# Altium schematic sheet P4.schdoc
size 297 x 209 mm; Symbol: Drawing-Symbol_A4; Company: 嘉立创EDA; Version: V1.0; Page Size: A4; @Project Name: 远程开机卡; @Update Date: 2026-06-19; @Create Date: 2026-06-19; Device: Drawing-Symbol_A4; @Board Name: cm4_1; @Page Name: P3; @Create Time: 20:06:20; @Page Count: 7; @Page No: 0; @Schematic Name: SCH_1; @Update Time: 20:06:20; @Assembly Variant: Basic; Border: 1; Title Block Position: 3; Size: A4; Width: 1170; Height: 825; Region Start: 1; X Region Count: 6; Y Region Count: 4; Blade Width: 10
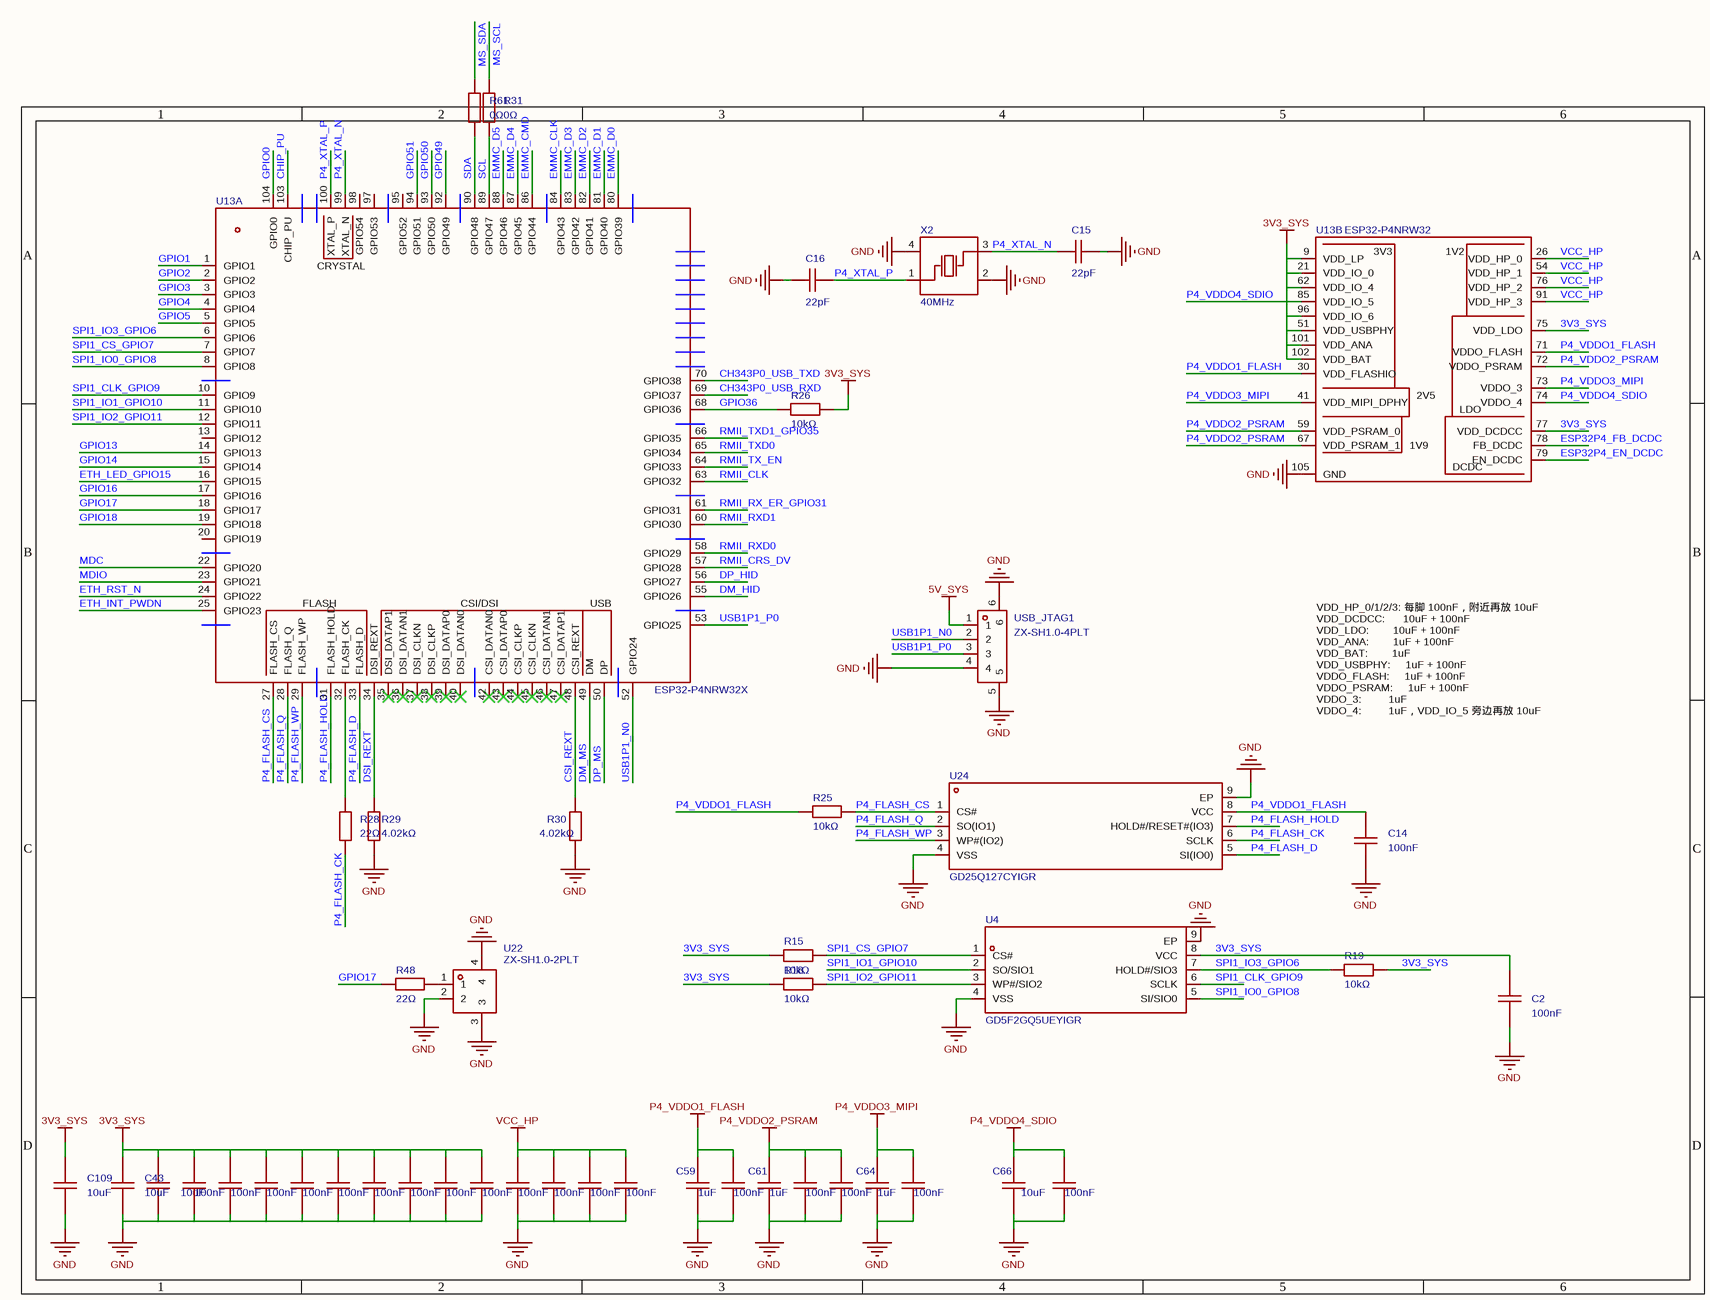
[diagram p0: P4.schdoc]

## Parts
C2  100nF  [C0402 去耦电容]
C14  100nF  [C0402 去耦电容]
C15  22pF  [C0402]
C16  22pF  [C0402]
C43  10uF  [C0805]
C44  10uF  [C0805]
C45  100nF  [C0402 去耦电容]
C46  100nF  [C0402 去耦电容]
C47  100nF  [C0402 去耦电容]
C48  100nF  [C0402 去耦电容]
C49  100nF  [C0402 去耦电容]
C50  100nF  [C0402 去耦电容]
C51  100nF  [C0402 去耦电容]
C52  100nF  [C0402 去耦电容]
C53  100nF  [C0402 去耦电容]
C55  100nF  [C0402 去耦电容]
C56  100nF  [C0402 去耦电容]
C57  100nF  [C0402 去耦电容]
C58  100nF  [C0402 去耦电容]
C59  1uF  [C0402]
C60  100nF  [C0402 去耦电容]
C61  1uF  [C0402]
C62  100nF  [C0402 去耦电容]
C63  100nF  [C0402 去耦电容]
C64  1uF  [C0402]
C65  100nF  [C0402 去耦电容]
C66  10uF  [C0805]
C67  100nF  [C0402 去耦电容]
C109  10uF  [C0805]
R15  10kΩ  [R0402]
R18  10kΩ  [R0402]
R19  10kΩ  [R0402]
R25  10kΩ  [R0402]
R26  10kΩ  [R0402]
R28  22Ω  [R0402]
R29  4.02kΩ  [R0402]
R30  4.02kΩ  [R0402]
R31  0Ω  [R0402]
R48  22Ω  [R0402]
R61  0Ω  [R0402]
U4  GD5F2GQ5UEYIGR  [WSON-8_L6.0-W8.0-P1.27-BL-EP]
U13  ESP32-P4NRW32X  [QFN-104_L10.0-W10.0-P0.35-TL-EP7.5]  (parts A,B of 2)
U22  ZX-SH1.0-2PLT  [CONN-SMD_2P-P1.00_MEGASTAR_ZX-SH1.0-2PLT]
U24  GD25Q127CYIGR  [WSON-8_L6.0-W8.0-P1.27-BL-EP]
USB_JTAG1  ZX-SH1.0-4PLT  [CONN-SMD_4P-P1.00_ZX-SH1.0-4PLN]
X2  40MHz  [OSC-SMD_4P-L3.2-W2.5-BL_SIT8008BI]

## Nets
3V3_SYS: C2.1 C43.2 C44.2 C45.2 C46.2 C47.2 C48.2 C49.2 C50.2 C51.2 C52.2 C53.2 C109.2 R15.1 R18.1 R19.2 R26.2 U4.8(VCC) U13.9(VDD_LP) U13.21(VDD_IO_0) U13.51(VDD_USBPHY) U13.62(VDD_IO_4) U13.75(VDD_LDO) U13.77(VDD_DCDCC) U13.96(VDD_IO_6) U13.101(VDD_ANA) U13.102(VDD_BAT)
5V_SYS: USB_JTAG1.1
GND: C2.2 C14.2 C15.2 C16.1 C43.1 C44.1 C45.1 C46.1 C47.1 C48.1 C49.1 C50.1 C51.1 C52.1 C53.1 C55.1 C56.1 C57.1 C58.1 C59.1 C60.1 C61.1 C62.1 C63.1 C64.1 C65.1 C66.1 C67.1 C109.1 R29.1 R30.1 U4.4(VSS) U4.9(EP) U13.105(GND) U22.2 U22.3 U22.4 U24.4(VSS) U24.9(EP) USB_JTAG1.4 USB_JTAG1.5 USB_JTAG1.6 X2.2(GND) X2.4(GND)
P4_VDDO1_FLASH: C14.1 C59.2 C60.2 R25.1 U13.30(VDD_FLASHIO) U13.71(VDDO_FLASH) U24.8(VCC)
P4_VDDO2_PSRAM: C61.2 C62.2 C63.2 U13.59(VDD_PSRAM_0) U13.67(VDD_PSRAM_1) U13.72(VDDO_PSRAM)
P4_VDDO3_MIPI: C64.2 C65.2 U13.41(VDD_MIPI_DPHY) U13.73(VDDO_3)
P4_VDDO4_SDIO: C66.2 C67.2 U13.74(VDDO_4) U13.85(VDD_IO_5)
VCC_HP: C55.2 C56.2 C57.2 C58.2 U13.26(VDD_HP_0) U13.54(VDD_HP_1) U13.76(VDD_HP_2) U13.91(VDD_HP_3)
CH343P0_USB_RXD: U13.69(GPIO37)
CH343P0_USB_TXD: U13.70(GPIO38)
CHIP_PU: U13.103(CHIP_PU)
CSI_REXT: R30.2 U13.48(CSI_REXT)
DM_HID: U13.55(GPIO26)
DM_MS: U13.49(DM)
DP_HID: U13.56(GPIO27)
DP_MS: U13.50(DP)
DSI_REXT: R29.2 U13.34(DSI_REXT)
EMMC_CLK: U13.84(GPIO43)
EMMC_CMD: U13.86(GPIO44)
EMMC_D0: U13.80(GPIO39)
EMMC_D1: U13.81(GPIO40)
EMMC_D2: U13.82(GPIO41)
EMMC_D3: U13.83(GPIO42)
EMMC_D4: U13.87(GPIO45)
EMMC_D5: U13.88(GPIO46)
ESP32P4_EN_DCDC: U13.79(EN_DCDC)
ESP32P4_FB_DCDC: U13.78(FB_DCDC)
ETH_INT_PWDN: U13.25(GPIO23)
ETH_LED_GPIO15: U13.16(GPIO15)
ETH_RST_N: U13.24(GPIO22)
GPIO0: U13.104(GPIO0)
GPIO1: U13.1(GPIO1)
GPIO2: U13.2(GPIO2)
GPIO3: U13.3(GPIO3)
GPIO4: U13.4(GPIO4)
GPIO5: U13.5(GPIO5)
GPIO13: U13.14(GPIO13)
GPIO14: U13.15(GPIO14)
GPIO16: U13.17(GPIO16)
GPIO17: R48.1 U13.18(GPIO17)
GPIO18: U13.19(GPIO18)
GPIO36: R26.1 U13.68(GPIO36)
GPIO49: U13.92(GPIO49)
GPIO50: U13.93(GPIO50)
GPIO51: U13.94(GPIO51)
MDC: U13.22(GPIO20)
MDIO: U13.23(GPIO21)
MS_SCL: R31.1
MS_SDA: R61.1
P4_FLASH_CK: R28.1 U24.6(SCLK)
P4_FLASH_CS: R25.2 U13.27(FLASH_CS) U24.1(CS#)
P4_FLASH_D: U13.33(FLASH_D) U24.5(SI(IO0))
P4_FLASH_HOLD: U13.31(FLASH_HOLD) U24.7(HOLD#/RESET#(IO3))
P4_FLASH_Q: U13.28(FLASH_Q) U24.2(SO(IO1))
P4_FLASH_WP: U13.29(FLASH_WP) U24.3(WP#(IO2))
P4_XTAL_N: C15.1 U13.99(XTAL_N) X2.3(OSC2)
P4_XTAL_P: C16.2 U13.100(XTAL_P) X2.1(OSC1)
RMII_CLK: U13.63(GPIO32)
RMII_CRS_DV: U13.57(GPIO28)
RMII_RX_ER_GPIO31: U13.61(GPIO31)
RMII_RXD0: U13.58(GPIO29)
RMII_RXD1: U13.60(GPIO30)
RMII_TX_EN: U13.64(GPIO33)
RMII_TXD0: U13.65(GPIO34)
RMII_TXD1_GPIO35: U13.66(GPIO35)
SCL: R31.2 U13.89(GPIO47)
SDA: R61.2 U13.90(GPIO48)
SPI1_CLK_GPIO9: U4.6(SCLK) U13.10(GPIO9)
SPI1_CS_GPIO7: R15.2 U4.1(CS#) U13.7(GPIO7)
SPI1_IO0_GPIO8: U4.5(SI/SIO0) U13.8(GPIO8)
SPI1_IO1_GPIO10: U4.2(SO/SIO1) U13.11(GPIO10)
SPI1_IO2_GPIO11: R18.2 U4.3(WP#/SIO2) U13.12(GPIO11)
SPI1_IO3_GPIO6: R19.1 U4.7(HOLD#/SIO3) U13.6(GPIO6)
USB1P1_N0: U13.52(GPIO24) USB_JTAG1.2
USB1P1_P0: U13.53(GPIO25) USB_JTAG1.3
NetR28_2: R28.2 U13.32(FLASH_CK)
NetR48_2: R48.2 U22.1

Not connected (* = marked no-connect by the designer): U13 13(GPIO12) 20(GPIO19) 35(DSI_DATAP1)* 36(DSI_DATAN1)* 37(DSI_CLKN)* 38(DSI_CLKP)* 39(DSI_DATAP0)* 40(DSI_DATAN0)* 42(CSI_DATAN0)* 43(CSI_DATAP0)* 44(CSI_CLKP)* 45(CSI_CLKN)* 46(CSI_DATAN1)* 47(CSI_DATAP1)* 95(GPIO52) 97(GPIO53) 98(GPIO54)

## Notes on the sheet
- VDD_HP_0/1/2/3: 每脚 100nF，附近再放 10uF
  VDD_DCDCC:      10uF + 100nF
  VDD_LDO:        10uF + 100nF
  VDD_ANA:        1uF + 100nF
  VDD_BAT:        1uF
  VDD_USBPHY:     1uF + 100nF
  VDDO_FLASH:     1uF + 100nF
  VDDO_PSRAM:     1uF + 100nF
  VDDO_3:         1uF
  VDDO_4:         1uF，VDD_IO_5 旁边再放 10uF

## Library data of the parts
C2 C14 = CL05B104KO5NNNC: 容值:100nF;精度:±10%;额定电压:16V;温度系数:X7R;; Manufacturer: SAMSUNG(三星); Check: false; Add into BOM: yes; 3D Model: 36a51122f27c49738f86b3bfa98863e0; 3D Model Transform: 39.37,19.685,0,0,0,0,0,0,0; Tolerance: ±10%; Voltage Rating: 16V; Temperature Coefficient: X7R; ModelName: C0402_L1.0-W0.5-H0.5
C15 C16 = 0402CG220J500NT: 容值:22pF;精度:±5%;额定电压:50V;温度系数:C0G;; Manufacturer: FH(风华); Add into BOM: yes; 3D Model: 36a51122f27c49738f86b3bfa98863e0; 3D Model Transform: 39.37,19.685,0,0,0,0,0,0,0; Tolerance: ±5%; Voltage Rating: 50V; Temperature Coefficient: C0G; ModelName: C0402_L1.0-W0.5-H0.5
C43 C44 C66 C109 = CL21A106KAYNNNE_C15850: 容值:10uF;精度:±10%;额定电压:25V;温度系数:X5R;; Manufacturer: SAMSUNG(三星); Add into BOM: yes; 3D Model: 1ba041120af144c991958decab20d241; 3D Model Transform: 78.74,51.181,0,0,0,0,0,0.0005,0; Tolerance: ±10%; Voltage Rating: 25V; Temperature Coefficient: X5R; ModelName: C0805_L2.0-W1.3-H1.3
C45-C53 C55-C58 C60 C62 C63 C65 C67 = CL05B104KO5NNNC: 容值:100nF;精度:±10%;额定电压:16V;温度系数:X7R;; Manufacturer: SAMSUNG(三星); Symbol: Capacitance; Check: false; Add into BOM: yes; 3D Model Transform: 39.37,19.685,0,0,0,0,0,0,0; Tolerance: ±10%; Voltage Rating: 16V; Temperature Coefficient: X7R; 3D Model: 36a51122f27c49738f86b3bfa98863e00819f05c4eef4c71ace90d822a990e87; ModelName: C0402_L1.0-W0.5-H0.5
C59 C61 C64 = CL05A105KA5NQNC: 容值:1uF;精度:±10%;额定电压:25V;温度系数:X5R;; Manufacturer: SAMSUNG(三星); Symbol: Capacitance; Add into BOM: yes; 3D Model: 36a51122f27c49738f86b3bfa98863e0; 3D Model Transform: 39.37,19.685,0,0,0,0,0,0,0; Tolerance: ±10%; Voltage Rating: 25V; Temperature Coefficient: X5R; ModelName: C0402_L1.0-W0.5-H0.5
R15 R18 R19 R25 R26 = 0402WGF1002TCE: 电阻类型:厚膜电阻;阻值:10kΩ;精度:±1%;功率:62.5mW;工作电压:50V;温度系数:±100ppm/℃;; Manufacturer: UNI-ROYAL(厚声); Add into BOM: yes; 3D Model: 98c88bc2b9094f218f3a3e30a7012738; 3D Model Transform: 39.37,19.685,0,0,0,0,0,0,0; Tolerance: ±1%; Power(Watts): 62.5mW; Voltage-Supply(Max): 50V; ModelName: R0402_L1.0-W0.5-H0.4
R28 R48 = 0402WGF220JTCE: 电阻类型:厚膜电阻;阻值:22Ω;精度:±1%;功率:62.5mW;最大工作电压:50V;温度系数:±100ppm/℃;; Manufacturer: UNI-ROYAL(厚声); Add into BOM: yes; 3D Model: 98c88bc2b9094f218f3a3e30a7012738; 3D Model Transform: 39.37,19.685,0,0,0,0,0,0,0; Tolerance: ±1%; Power(Watts): 62.5mW; Overload Voltage (Max): 50V; ModelName: R0402_L1.0-W0.5-H0.4
R29 R30 = RMC04024.02K1%N: 电阻类型:厚膜电阻;阻值:4.02kΩ;精度:±1%;功率:62.5mW;工作电压:50V;温度系数:±100ppm/℃;; Manufacturer: Tyohm(幸亚电阻); Symbol: 电阻; Add into BOM: yes; 3D Model Transform: 39.37,19.685,0,0,0,0,0,0,0; Tolerance: ±1%; Power(Watts): 62.5mW; Voltage-Supply(Max): 50V; 3D Model: 98c88bc2b9094f218f3a3e30a70127380819f05c4eef4c71ace90d822a990e87; ModelName: R0402_L1.0-W0.5-H0.4
R31 R61 = 0402WGF0000TCE: 电阻类型:厚膜电阻;阻值:0Ω;精度:±1%;功率:62.5mW;工作电压:50V;温度系数:±800ppm/℃;; Manufacturer: UNI-ROYAL(厚声); Add into BOM: yes; 3D Model: 98c88bc2b9094f218f3a3e30a7012738; 3D Model Transform: 39.37,19.685,0,0,0,0,0,0,0; Tolerance: ±1%; Power(Watts): 62.5mW; Voltage-Supply(Max): 50V; ModelName: R0402_L1.0-W0.5-H0.4
U4 = GD5F2GQ5UEYIGR: 存储容量:2Gbit;时钟频率(fc):104MHz;工作电压:2.7V~3.6V;; Manufacturer: GigaDevice(兆易创新); AddInBom: yes; ModelId: b173dc61e57d4be286a8c115df50567b0819f05c4eef4c71ace90d822a990e87; ModelName: WSON-8_L6.0-W8.0-H0.8-P1.27; ModelTransform: 315.7474,236.22,0,90,0,0,0.005,0.016,0; Memory Size: 2Gbit; Interface: SPI; Clock Frequency: 104MHz; Page Program time (TPP): 300us; Block Erase Time(tBE): 3ms; Data Retention - TDR (Year): 10年; Standby Supply Current: 50uA; Program / Erase Cycles: 10万次
U13 = ESP32-P4NRW32_C22387510: 是一款高性能 MCU，支持超大片上内存，具有强大的图像和语音处理能力。该款 MCU 包含一个高性能（HP）系统和一个低功耗（LP）系统。HP 系统由 RISC-V 双核处理器驱动，包含丰富的外设；LP 系统由 RISC-V 单核处理器驱动，其外设针对低功耗应用进行了优化。; Manufacturer: ESPRESSIF(乐鑫); Check: false; Relevance: []; Add into BOM: yes; 3D Model: 754e858a1a6d4da4ad54dc5f9780675c0819f05c4eef4c71ace90d822a990e87; 3D Model Transform: 394.487,394.487,0,0,0,0,0,0,0
U22 = ZX-SH1.0-2PLT: 插针结构:1x2P;间距:1mm;安装方式:立贴;参考系列:SH;总PIN数:2P;排数:1;每排PIN数:2;行距:-;额定电流:1A;触头材质:黄铜;触头镀层:锡;工作温度:-40℃~+85℃;; Manufacturer: Megastar(兆星); AddInBom: yes; ModelId: eb28ac50c0d04ec997784b2fd7fdd91e0819f05c4eef4c71ace90d822a990e87; ModelTransform: 171.2595,147.638,0,180,0,0,0,11.966,0; Pins Structure: 1x2P; Pitch: 1mm; Reference Series: SH; Number of PINs Per Row: 2; Current Rating: 1A; Voltage Rating: 50V; Plastic Material: LCP; Supplementary Features: 辅助焊脚; Z-Height of the Board: 4.4mm; X-Length of Bottom Edge on Board (Spacing Line): 4.35mm; Y-Width of Bottom Edge on Board: 3.05mm
U24 = GD25Q127CYIGR: 接口类型:SPI;存储容量:128Mbit;时钟频率(fc):104MHz;; Manufacturer: GigaDevice(兆易创新); AddInBom: yes; ModelId: b173dc61e57d4be286a8c115df50567b0819f05c4eef4c71ace90d822a990e87; ModelName: WSON-8_L6.0-W8.0-H0.8-P1.27; ModelTransform: 315.7474,236.22,0,90,0,0,0.005,0.016,0; Interface: SPI; Clock Frequency: 104MHz; Voltage - Supply: 2.7V~3.6V; Standby Supply Current: 20uA; Program / Erase Cycles: 100000次; Page Programming Time (Tpp): 500us; Data Retention - TDR (Year): 20年
USB_JTAG1 = ZX-SH1.0-4PLT: 插针结构:1x4P;间距:1mm;安装方式:立贴;参考系列:SH;总PIN数:4P;排数:1;每排PIN数:4;行距:-;额定电流:1A;触头材质:黄铜;触头镀层:锡;工作温度:-40℃~+85℃;; Manufacturer: Megastar(兆星); Add into BOM: yes; 3D Model: 8007957c7583430d838950316d828607; 3D Model Transform: 249.9995,147.638,0,0,0,0,0.003,-14.607,0; Pins Structure: 1x4P; Pitch: 1mm; Reference Series: SH; Number of PINs Per Row: 4; Current Rating: 1A; Voltage Rating: 50V; Plastic Material: LCP; Supplementary Features: 辅助焊脚; Z-Height of the Board: 4.4mm; X-Length of Bottom Edge on Board (Spacing Line): 6.35mm; Y-Width of Bottom Edge on Board: 3.05mm
X2 = X322540MPB4SI: 晶振类型:贴片晶振;频率:40MHz;常温频差:±10ppm;负载电容:15pF;频率稳定度:±20ppm;; Manufacturer: YXC(扬兴晶振); 3D Model: ae22b8d143894765bc8100c37cb6356f0819f05c4eef4c71ace90d822a990e87; 3D Model Transform: 125.984,98.425,0,0,0,0,0,0,0; Normal temperature Frequency Tolerance: ±10ppm; Load Capacitance: 15pF; Frequency Stability: ±20ppm; AddInBom: yes; ModelName: OSC-SMD_4P-L3.2-W2.5-H1.0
